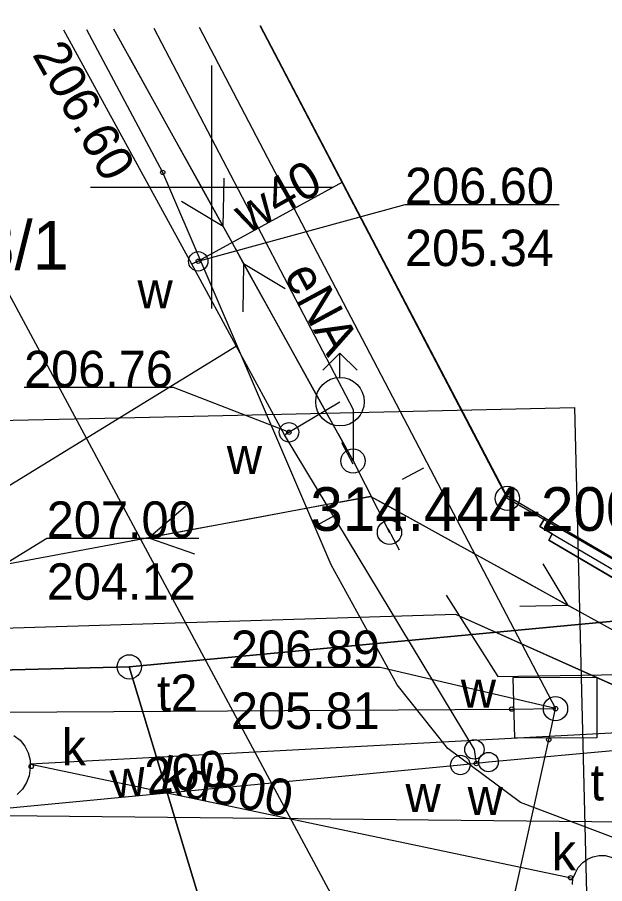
# Model space of a CAD drawing. Extents: x 6512400 to 6513200, y 6022500 to 6022750.
# Drawn here: x 6512795.99 to 6512808.09, y 6022685.66 to 6022703.49 of the extents above; entities that cross this region are included whole.
import ezdxf

# ---------------------------------------------------------------- set-up
doc = ezdxf.new("R2010")
doc.units = 0
for name, color, linetype in [('122-Punkt osnowy szczegółowej-Atr103', 7, 'Continuous'), ('202-punkt graniczny', 7, 'Continuous'), ('211-numer działki ewidencyjnej', 7, 'Continuous'), ('217-kontur klasyfikacyjny', 7, 'Continuous'), ('218-kontur użytku gruntowego', 7, 'Continuous'), ('219-działka ewidencyjna', 7, 'Continuous'), ('312-budynek ewidencyjny', 7, 'Continuous'), ('352-schody', 7, 'Continuous'), ('chodnik (powierzchnia)', 7, 'Continuous'), ('hydrant (punkt)', 7, 'Continuous'), ('inna obudowa przewodu - sieć gazowa (linia)', 7, 'Continuous'), ('inna obudowa przewodu - sieć telekomunikacyjna (linia)', 7, 'Continuous'), ('komora podziemna - przewód kanalizacyjny (powierzchnia)', 7, 'Continuous'), ('komora podziemna - przewód telekomunikacyjny (powierzchnia)', 7, 'Continuous'), ('krawężnik (linia)', 7, 'Continuous'), ('latarnia na słupie lub maszcie (punkt)', 7, 'Continuous'), ('Obszar opracowania', 7, 'Continuous'), ('przewód elektroenergetyczny (linia)', 7, 'Continuous'), ('przewód elektroenergetyczny (linia)-Atr1', 7, 'Continuous'), ('przewód elektroenergetyczny niskiego napięcia (linia)', 7, 'Continuous'), ('przewód elektroenergetyczny niskiego napięcia (linia) - symbol', 7, 'Continuous'), ('przewód gazowy (linia)', 7, 'Continuous'), ('przewód kanalizacyjny (linia)', 7, 'Continuous'), ('przewód kanalizacyjny (linia)-Atr1', 7, 'Continuous'), ('przewód telekomunikacyjny (linia)', 7, 'Continuous'), ('przewód telekomunikacyjny (linia)-Atr1', 7, 'Continuous'), ('przewód wodociągowy (linia)', 7, 'Continuous'), ('przewód wodociągowy (linia)-Atr1', 7, 'Continuous'), ('punkt o określonej wysokości (sieć gazowa)-Atr2', 7, 'Continuous'), ('punkt o określonej wysokości (sieć gazowa)-Atr3', 7, 'Continuous'), ('punkt o określonej wysokości (sieć kanalizacyjna)', 7, 'Continuous'), ('punkt o określonej wysokości (sieć telekomunikacyjna)', 7, 'Continuous'), ('punkt o określonej wysokości (sieć telekomunikacyjna)-Atr2', 7, 'Continuous'), ('punkt o określonej wysokości (sieć telekomunikacyjna)-Atr3', 7, 'Continuous'), ('punkt o określonej wysokości (sieć wodociągowa)', 7, 'Continuous'), ('punkt o określonej wysokości (sieć wodociągowa)-Atr2', 7, 'Continuous'), ('punkt o określonej wysokości (sieć wodociągowa)-Atr3', 7, 'Continuous'), ('punkt wysokościowy sztuczny', 7, 'Continuous'), ('punkt wysokościowy sztuczny-Atr2', 7, 'Continuous'), ('słup łączony (linia)', 7, 'Continuous'), ('słup łączony (linia) - symbol', 7, 'Continuous'), ('Wstawianie ramki sekcyjnej z opisem', 7, 'Continuous'), ('właz okrągły - siec kanalizacyjna (punkt)-Atr17', 7, 'Continuous'), ('właz okrągły - siec telekomunikacyjna (punkt)', 7, 'Continuous'), ('właz okrągły - siec telekomunikacyjna (punkt)-Atr17', 7, 'Continuous'), ('zasuwa - siec wodociągowa (punkt)', 7, 'Continuous'), ('zasuwa - siec wodociągowa (punkt)-Atr17', 7, 'Continuous')]:
    doc.layers.add(name, color=color, linetype=linetype)

# ---------------------------------------------------------------- blocks, each defined once
blk = doc.blocks.new('202')
blk.add_circle((0, 0), 0.25)
blk = doc.blocks.new('PE04')
for p, q in [((4.65, 0), (3.784, 0.5)), ((0.65, 0), (0, 0)), ((0.65, 0), (1.65, 0)), ((1.65, 0), (2.65, 0)), ((2.65, 0), (3.65, 0)), ((3.65, 0), (4.65, 0)), ((4.65, 0), (3.784, -0.5)), ((4.65, 0), (5, 0))]:
    blk.add_line(p, q)
blk = doc.blocks.new('PW01')
blk.add_circle((0, 0), 0.045)
blk = doc.blocks.new('US22')
blk.add_circle((0, 0), 0.25)
blk = doc.blocks.new('SM05')
blk.add_circle((0, 0), 0.25)
blk = doc.blocks.new('SM011')
for p, q in [((-0.53, 0.531), (-0.883, 0.884)), ((0.531, 0.531), (0.884, 0.884)), ((-0.53, -0.53), (-0.883, -0.883)), ((0.531, -0.53), (0.884, -0.883))]:
    blk.add_line(p, q)
blk = doc.blocks.new('US25')
blk.add_circle((0, 0), 0.2)
blk = doc.blocks.new('US02')
for p, q in [((0, 1), (-0.353, 0.647)), ((0, 0.5), (0, 1)), ((0, 1), (0.354, 0.647))]:
    blk.add_line(p, q)
blk.add_circle((0, 0), 0.5)
blk = doc.blocks.new('PW02')
blk.add_circle((0, 0), 0.045)
blk = doc.blocks.new('RAMKA500K')
for p, q in [((0, 197.5), (0, 202.5)), ((400, 197.5), (400, 202.5)), ((0, 200), (2.5, 200)), ((397.5, 200), (400, 200))]:
    blk.add_line(p, q)

msp = doc.modelspace()

# ---------------------------------------------------------------- linework, layer by layer
at = {"layer": '217-kontur klasyfikacyjny'}
for points in [[(6512800.998, 6022703.319), (6512806.09, 6022693.59)], [(6512806.09, 6022693.59), (6512810.17, 6022691.24)]]:
    msp.add_lwpolyline(points, dxfattribs=at)
at = {"layer": '218-kontur użytku gruntowego'}
for points in [[(6512806.09, 6022693.59), (6512800.998, 6022703.319)], [(6512800.998, 6022703.319), (6512806.09, 6022693.59)], [(6512810.17, 6022691.24), (6512806.09, 6022693.59)], [(6512806.09, 6022693.59), (6512810.17, 6022691.24)], [(6512798.3, 6022690.12), (6512810.17, 6022691.24)], [(6512810.17, 6022691.24), (6512798.3, 6022690.12)], [(6512793.2, 6022689.99), (6512798.3, 6022690.12)], [(6512798.3, 6022690.12), (6512793.2, 6022689.99)], [(6512798.3, 6022690.12), (6512802.61, 6022675.86)], [(6512802.61, 6022675.86), (6512798.3, 6022690.12)]]:
    msp.add_lwpolyline(points, dxfattribs=at)
at = {"layer": '219-działka ewidencyjna'}
for points in [[(6512806.09, 6022693.59), (6512800.998, 6022703.319)], [(6512810.17, 6022691.24), (6512806.09, 6022693.59)], [(6512798.3, 6022690.12), (6512810.17, 6022691.24)], [(6512798.3, 6022690.12), (6512793.2, 6022689.99)], [(6512802.61, 6022675.86), (6512798.3, 6022690.12)]]:
    msp.add_lwpolyline(points, dxfattribs=at)
at = {"layer": '312-budynek ewidencyjny'}
for points in [[(6512806.08, 6022693.64), (6512801.001, 6022703.319)], [(6512810.11, 6022691.27), (6512806.08, 6022693.64)]]:
    msp.add_lwpolyline(points, dxfattribs=at)
at = {"layer": '352-schody'}
for p, q in [((6512806.86, 6022693.18), (6512806.76, 6022693.01)), ((6512809.32, 6022691.74), (6512806.86, 6022693.18)), ((6512806.76, 6022693.01), (6512807.01, 6022692.86)), ((6512807.01, 6022692.86), (6512806.94, 6022692.73)), ((6512806.94, 6022692.73), (6512808.97, 6022691.54)), ((6512807.01, 6022692.86), (6512809.04, 6022691.67))]:
    msp.add_line(p, q, dxfattribs=at)
at = {"layer": 'chodnik (powierzchnia)'}
msp.add_lwpolyline([(6512810.11, 6022691.27), (6512809.32, 6022691.74), (6512809.22, 6022691.57), (6512809.04, 6022691.67), (6512808.97, 6022691.54), (6512806.94, 6022692.73), (6512807.01, 6022692.86), (6512806.76, 6022693.01), (6512806.86, 6022693.18), (6512806.08, 6022693.64), (6512801.003, 6022703.319)], dxfattribs=at)
at = {"layer": 'inna obudowa przewodu - sieć gazowa (linia)'}
msp.add_lwpolyline([(6512808.9, 6022689.46), (6512805.03, 6022691.2), (6512793.46, 6022690.84)], dxfattribs=at)
at = {"layer": 'inna obudowa przewodu - sieć telekomunikacyjna (linia)'}
for points in [[(6512794.41, 6022689.18), (6512794.46, 6022689.18), (6512806.18, 6022689.25), (6512806.23, 6022689.25)], [(6512803.35, 6022672.37), (6512803.36, 6022672.42), (6512806.94, 6022688.62), (6512806.95, 6022688.66)]]:
    msp.add_lwpolyline(points, dxfattribs=at)
at = {"layer": 'komora podziemna - przewód kanalizacyjny (powierzchnia)'}
for points in [[(6512795.92, 6022688.71), (6512796.05, 6022688.61), (6512796.15, 6022688.49), (6512796.22, 6022688.35), (6512796.26, 6022688.2), (6512796.26, 6022688.04), (6512796.24, 6022687.88), (6512796.18, 6022687.74), (6512796.1, 6022687.6), (6512795.99, 6022687.49)], [(6512807.43, 6022685.64), (6512807.44, 6022685.76), (6512807.49, 6022685.88), (6512807.55, 6022685.99), (6512807.64, 6022686.09), (6512807.74, 6022686.16), (6512807.85, 6022686.21), (6512807.98, 6022686.24), (6512808.1, 6022686.24), (6512808.23, 6022686.2), (6512808.34, 6022686.15), (6512808.44, 6022686.08), (6512808.53, 6022685.98), (6512808.59, 6022685.87), (6512808.62, 6022685.75), (6512808.63, 6022685.63)]]:
    msp.add_lwpolyline(points, dxfattribs=at)
at = {"layer": 'komora podziemna - przewód telekomunikacyjny (powierzchnia)'}
msp.add_lwpolyline([(6512806.24, 6022688.65), (6512806.21, 6022689.9), (6512807.93, 6022689.91), (6512807.93, 6022688.66)], close=True, dxfattribs=at)
at = {"layer": 'krawężnik (linia)'}
msp.add_lwpolyline([(6512810.65, 6022686.18), (6512808.52, 6022686.51), (6512806.36, 6022687.33), (6512804.86, 6022688.44), (6512803.82, 6022689.75), (6512802.46, 6022692.22), (6512798.99, 6022700.3), (6512797.428, 6022703.239)], dxfattribs=at)
at = {"layer": 'Obszar opracowania'}
msp.add_lwpolyline([(6512710.98, 6022693.84), (6512748.35, 6022694.16), (6512798.11, 6022695.25), (6512807.47, 6022695.46), (6512809.66, 6022606.87), (6512863.71, 6022622.03), (6512875.13, 6022581.36), (6512755.22, 6022535.25), (6512691.61, 6022568.03), (6512709.16, 6022605.16)], close=True, dxfattribs=at)
at = {"layer": 'przewód elektroenergetyczny (linia)'}
for points in [[(6512798.809, 6022703.27), (6512802.91, 6022695.42), (6512802.91, 6022694.36)], [(6512804.83, 6022691.6), (6512805.89, 6022689.92), (6512810.59, 6022690), (6512816.98, 6022689.19), (6512818.13, 6022690.17), (6512819.01, 6022690.24), (6512819.69, 6022689.7), (6512825.585, 6022689.929)], [(6512827.998, 6022686.723), (6512793.03, 6022687.08), (6512782.71, 6022686.93), (6512780.71, 6022686.29)]]:
    msp.add_lwpolyline(points, dxfattribs=at)
at = {"layer": 'przewód elektroenergetyczny niskiego napięcia (linia)'}
for points in [[(6512802.91, 6022694.36), (6512797.982, 6022703.251)], [(6512803.27, 6022693.63), (6512782.09, 6022689.68)], [(6512814.78, 6022687.29), (6512803.27, 6022693.63)]]:
    msp.add_lwpolyline(points, dxfattribs=at)
at = {"layer": 'przewód gazowy (linia)'}
msp.add_lwpolyline([(6512808.91, 6022689.46), (6512805.03, 6022691.2), (6512793.46, 6022690.84)], dxfattribs=at)
at = {"layer": 'przewód kanalizacyjny (linia)'}
for points in [[(6512803.88, 6022681.97), (6512803.01, 6022684.42), (6512792.949, 6022703.141)], [(6512823.6, 6022689.9), (6512818.78, 6022689.32), (6512796.26, 6022688.12)], [(6512807.44, 6022685.76), (6512796.27, 6022688.11)]]:
    msp.add_lwpolyline(points, dxfattribs=at)
at = {"layer": 'przewód telekomunikacyjny (linia)'}
for points in [[(6512799.742, 6022703.291), (6512807.08, 6022689.26)], [(6512793.56, 6022689.17), (6512794.46, 6022689.18), (6512806.18, 6022689.25), (6512807.08, 6022689.26)], [(6512803.2, 6022671.69), (6512803.36, 6022672.42), (6512806.94, 6022688.62), (6512807.08, 6022689.26)]]:
    msp.add_lwpolyline(points, dxfattribs=at)
at = {"layer": 'przewód wodociągowy (linia)'}
for points in [[(6512805.45, 6022688.13), (6512805.41, 6022688.42), (6512801.5, 6022694.9), (6512799.59, 6022698.41), (6512796.954, 6022703.229)], [(6512802.69, 6022700.1), (6512799.72, 6022698.47), (6512799.59, 6022698.41)], [(6512800.51, 6022696.72), (6512794.8, 6022693.22)], [(6512801.5, 6022694.9), (6512801.59, 6022694.95), (6512802.64, 6022695.58)], [(6512828.176, 6022686.486), (6512808.56, 6022688.42), (6512805.7, 6022688.16), (6512805.45, 6022688.13)], [(6512805.45, 6022688.13), (6512805.12, 6022688.1), (6512792.38, 6022686.88), (6512788.46, 6022686.58), (6512782.96, 6022686.75), (6512777.64, 6022686.77), (6512777.27, 6022686.75)]]:
    msp.add_lwpolyline(points, dxfattribs=at)
at = {"layer": 'punkt o określonej wysokości (sieć gazowa)-Atr2'}
msp.add_lwpolyline([(6512793.46, 6022690.84), (6512796.6, 6022692.77), (6512799.73, 6022692.77)], dxfattribs=at)
at = {"layer": 'punkt o określonej wysokości (sieć telekomunikacyjna)-Atr2'}
msp.add_lwpolyline([(6512807.08, 6022689.26), (6512803.47, 6022690.11), (6512800.393, 6022690.11)], dxfattribs=at)
at = {"layer": 'punkt o określonej wysokości (sieć wodociągowa)-Atr2'}
for points in [[(6512799.72, 6022698.47), (6512803.98, 6022699.64), (6512807.153, 6022699.64)], [(6512801.59, 6022694.95), (6512799.21, 6022695.87), (6512796.133, 6022695.87)]]:
    msp.add_lwpolyline(points, dxfattribs=at)
at = {"layer": 'słup łączony (linia)'}
msp.add_lwpolyline([(6512802.91, 6022694.36), (6512803.66, 6022692.89)], dxfattribs=at)

# ---------------------------------------------------------------- block references
at = {"layer": '202-punkt graniczny'}
for p in [(6512806.09, 6022693.59), (6512798.3, 6022690.12)]:
    msp.add_blockref('202', p, dxfattribs=at)
at = {"layer": 'hydrant (punkt)'}
msp.add_blockref('US02', (6512802.64, 6022695.58), dxfattribs=at)
at = {"layer": 'latarnia na słupie lub maszcie (punkt)', "rotation": 73.171}
msp.add_blockref('SM011', (6512803.27, 6022693.63), dxfattribs=at)
at = {"layer": 'przewód elektroenergetyczny niskiego napięcia (linia) - symbol'}
for p, rotation in [((6512797.982, 6022703.251), -61.002), ((6512802.91, 6022694.36), 118.998), ((6512803.27, 6022693.63), -169.43600000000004), ((6512803.27, 6022693.63), -28.846999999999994)]:
    msp.add_blockref('PE04', p, dxfattribs=dict(at, rotation=rotation))
at = {"layer": 'punkt o określonej wysokości (sieć kanalizacyjna)'}
msp.add_blockref('PW01', (6512796.28, 6022688.07), dxfattribs=at)
at = {"layer": 'punkt o określonej wysokości (sieć kanalizacyjna)', "rotation": -11.054}
msp.add_blockref('PW01', (6512807.39, 6022685.78), dxfattribs=at)
at = {"layer": 'punkt o określonej wysokości (sieć telekomunikacyjna)'}
for p, rotation in [((6512806.18, 6022689.25), 1.1869999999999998), ((6512806.94, 6022688.62), 78.325)]:
    msp.add_blockref('PW01', p, dxfattribs=dict(at, rotation=rotation))
msp.add_blockref('PW01', (6512807.08, 6022689.26), dxfattribs=at)
at = {"layer": 'punkt o określonej wysokości (sieć wodociągowa)'}
for p, rotation in [((6512799.72, 6022698.47), 29.514), ((6512801.59, 6022694.95), 29.055)]:
    msp.add_blockref('PW01', p, dxfattribs=dict(at, rotation=rotation))
msp.add_blockref('PW01', (6512805.45, 6022688.13), dxfattribs=at)
at = {"layer": 'punkt wysokościowy sztuczny'}
msp.add_blockref('PW02', (6512798.99, 6022700.3), dxfattribs=at)
at = {"layer": 'słup łączony (linia) - symbol'}
for p in [(6512802.91, 6022694.36), (6512803.66, 6022692.89)]:
    msp.add_blockref('SM05', p, dxfattribs=at)
at = {"layer": 'Wstawianie ramki sekcyjnej z opisem'}
for p in [(6512400, 6022500), (6512800, 6022500)]:
    msp.add_blockref('RAMKA500K', p, dxfattribs=at)
at = {"layer": 'właz okrągły - siec telekomunikacyjna (punkt)'}
msp.add_blockref('US22', (6512807.08, 6022689.26), dxfattribs=at)
at = {"layer": 'zasuwa - siec wodociągowa (punkt)'}
for p, rotation in [((6512799.72, 6022698.47), 29.514), ((6512801.59, 6022694.95), 29.055), ((6512805.41, 6022688.42), -58.075), ((6512805.12, 6022688.1), 6.911), ((6512805.7, 6022688.16), 5.988)]:
    msp.add_blockref('US25', p, dxfattribs=dict(at, rotation=rotation))

# ---------------------------------------------------------------- texts
at = {"layer": '122-Punkt osnowy szczegółowej-Atr103'}
msp.add_text('314.444-2003', height=0.9, dxfattribs=at).set_placement((6512802.03, 6022692.92))
at = {"layer": '211-numer działki ewidencyjnej'}
msp.add_text('58/1', height=1, dxfattribs=at).set_placement((6512794.45, 6022698.3))
at = {"layer": 'przewód elektroenergetyczny (linia)-Atr1'}
msp.add_text('eNA', height=0.75, rotation=298.355, dxfattribs=at).set_placement((6512801.47, 6022698.19))
at = {"layer": 'przewód kanalizacyjny (linia)-Atr1'}
msp.add_text('kd800', height=0.75, rotation=348.937, dxfattribs=at).set_placement((6512798.9, 6022687.55))
at = {"layer": 'przewód telekomunikacyjny (linia)-Atr1'}
msp.add_text('t2', height=0.75, rotation=1.187, dxfattribs=at).set_placement((6512798.88, 6022689.2))
at = {"layer": 'przewód wodociągowy (linia)-Atr1'}
for s, rotation, p in [('w40', 29.488, (6512800.73, 6022699.03)), ('w200', 6.281, (6512797.95, 6022687.41))]:
    msp.add_text(s, height=0.75, rotation=rotation, dxfattribs=at).set_placement(p)
at = {"layer": 'punkt o określonej wysokości (sieć gazowa)-Atr2'}
msp.add_text('207.00', height=0.75, dxfattribs=at).set_placement((6512796.6, 6022692.777))
at = {"layer": 'punkt o określonej wysokości (sieć gazowa)-Atr3'}
msp.add_text('204.12', height=0.75, dxfattribs=at).set_placement((6512796.6, 6022691.502))
at = {"layer": 'punkt o określonej wysokości (sieć telekomunikacyjna)-Atr2'}
msp.add_text('206.89', height=0.75, dxfattribs=at).set_placement((6512800.393, 6022690.118))
at = {"layer": 'punkt o określonej wysokości (sieć telekomunikacyjna)-Atr3'}
msp.add_text('205.81', height=0.75, dxfattribs=at).set_placement((6512800.393, 6022688.843))
at = {"layer": 'punkt o określonej wysokości (sieć wodociągowa)-Atr2'}
for s, p in [('206.60', (6512803.98, 6022699.647)), ('206.76', (6512796.133, 6022695.878))]:
    msp.add_text(s, height=0.75, dxfattribs=at).set_placement(p)
at = {"layer": 'punkt o określonej wysokości (sieć wodociągowa)-Atr3'}
msp.add_text('205.34', height=0.75, dxfattribs=at).set_placement((6512803.98, 6022698.372))
at = {"layer": 'punkt wysokościowy sztuczny-Atr2'}
msp.add_text('206.60', height=0.75, rotation=299.452, dxfattribs=at).set_placement((6512796.29, 6022702.73))
at = {"layer": 'właz okrągły - siec kanalizacyjna (punkt)-Atr17'}
for p in [(6512796.91, 6022688.09), (6512807, 6022685.93)]:
    msp.add_text('k', height=0.75, dxfattribs=at).set_placement(p)
at = {"layer": 'właz okrągły - siec telekomunikacyjna (punkt)-Atr17'}
msp.add_text('t', height=0.75, dxfattribs=at).set_placement((6512807.8, 6022687.37))
at = {"layer": 'zasuwa - siec wodociągowa (punkt)-Atr17'}
for p in [(6512798.47, 6022697.5), (6512800.31, 6022694.09), (6512805.13, 6022689.28), (6512803.99, 6022687.13), (6512805.27, 6022687.07)]:
    msp.add_text('w', height=0.75, dxfattribs=at).set_placement(p)

doc.saveas('drawing.dxf')
